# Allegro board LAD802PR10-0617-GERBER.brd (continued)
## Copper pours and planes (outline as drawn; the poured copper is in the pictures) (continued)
GND on BOTTOM (solid shape): 118.24,72.2 118.24,72 118.5,71.74 118.5,69.01 118.31,68.82 117.8,68.82 117.61,69.01 117.61,69.49 117.61,69.5 117.63,69.61 117.61,69.72 117.61,69.73 117.61,70.14 117.61,70.15 117.63,70.26 117.61,70.37 117.61,70.38 117.61,70.79 117.61,70.8 117.63,70.91 117.61,71.02 117.61,71.03 117.61,71.44 117.61,71.45 117.63,71.56 117.61,71.67 117.61,71.68 117.61,72.09 117.63,72.15 117.63,72.2 117.76,72.32 118.12,72.32
GND on BOTTOM (solid shape): 138.3,8.05 141.8,10.3 145.41,8.22 147.9,3.66 147.9,0.25 134.52,0.25
GND on BOTTOM (solid shape): 181.44,44.53 181.44,43.28 181.03,42.87 181.03,41.84 180.83,41.63 180.47,41.63 180.11,41.99 179.6,41.99 179.53,42.06 179.53,42.63 179.41,42.75 178.71,42.75 178.58,42.63 178.58,41.29 178.52,41.23 178.14,41.23 178.07,41.29 178.07,42.12 177.75,42.44 176.55,42.44 176.17,42.06 175.02,42.06 174.65,42.44 173.57,42.44 173.38,42.25 173.38,42.06 173.25,41.93 172.8,41.93 172.61,42.12 172.61,42.56 172.8,42.75 174.7,42.75 175.15,43.2 177.56,43.2 177.82,43.46 177.82,43.65 178.2,44.03 179.86,44.03 180.04,44.21 180.04,44.72 179.47,45.29 177.88,45.29 177.88,45.55 177.82,45.61 177.44,45.61 177.31,45.74 177.31,46.63 177.44,46.75 179.22,46.75
GND on BOTTOM (solid shape): 103.74,45.13 103.75,45.12 103.97,45.03 104.19,45.13 104.39,45.13 104.61,45.03 104.84,45.13 105.04,45.13 105.26,45.03 105.49,45.13 105.69,45.13 105.91,45.03 106.14,45.13 106.32,45.13 106.52,44.93 106.52,44.9 106.58,44.69 106.74,44.55 106.78,44.54 106.78,44.34 106.74,44.32 106.64,44.26 106.57,44.17 106.46,44.07 106.46,43.81 106.04,43.39 106,43.38 105.96,43.36 105.79,43.36 105.32,43.83 105.32,44.19 105.18,44.33 103.72,44.33 103.64,44.34 103.57,44.33 103.34,44.33 103.1,44.57 103.1,44.59 103.01,44.77 102.83,44.85 102.8,44.88 102.8,45.3 102.88,45.39 103.48,45.39
GND on BOTTOM (solid shape): 105.08,67.04 105.26,66.98 105.45,67.04 105.73,67.04 105.91,66.98 106.1,67.04 106.38,67.04 106.4,67.03 106.46,67 106.46,66.7 106.74,66.43 106.74,66.26 106.7,66.25 106.63,66.21 106.57,66.16 106.5,66.13 106.42,66.16 106.17,66.27 105.92,66.17 105.85,66.14 105.54,66.27 105.22,66.14 105.15,66.17 104.87,66.27 104.61,66.12 104.57,66.13 104.54,66.15 104.34,66.35 104.34,66.48 104.55,66.62 104.62,66.86 104.62,66.88 104.74,67.01 104.8,67.04
GND on BOTTOM (solid shape): outline of 91 points within 109.8,68.76 111.58,73.42
GND on BOTTOM (solid shape): outline of 153 points within 186.96,11.13 205.44,17.71
GND on BOTTOM (solid shape): 110.15,45.62 110.15,43.55 110.21,43.5 110.21,43.49 110.32,43.36 110.47,43.31 110.49,43.31 110.56,43.24 110.56,43.22 110.6,43.09 110.69,43 110.69,42.92 110.59,42.78 110.56,42.61 110.53,42.61 110.19,42.35 110.45,42.01 110.47,42.01 110.56,41.93 110.56,41.91 110.61,41.78 110.71,41.68 110.75,41.61 110.72,41.53 110.62,41.43 110.37,41.43 110.06,41.73 109.95,41.73 109.84,41.9 109.65,41.97 109.61,41.97 109.59,42 109.44,42.27 109.14,42.33 109.12,42.36 109.11,42.38 109.06,42.49 108.97,42.57 108.97,42.7 109.12,42.96 108.97,43.22 108.97,43.3 108.85,43.42 108.73,43.42 108.71,43.45 108.4,43.64 108.08,43.45 108.07,43.42 107.88,43.42 107.79,43.5 107.79,43.67 108.12,43.99 108.13,43.99 108.67,43.99 108.68,43.99 109.11,44.17 108.86,44.56 108.85,44.57 108.75,44.67 108.72,44.74 108.72,45.1 108.74,45.17 108.76,45.24 108.8,45.28 108.82,45.28 108.96,45.32 109.06,45.42 109.07,45.43 109.24,45.57 109.26,45.57 109.41,45.62 109.51,45.73 110.04,45.73
GND on BOTTOM (solid shape): outline of 206 points within 0.25,119.31 11.7,125.05
GND on BOTTOM (solid shape): outline of 110 points within 223.48,36.02 229.04,52.28
GND on BOTTOM (solid shape): 107.14,72.05 107.3,72.05 107.43,71.92 107.43,71.42 107.42,71.41 107.39,71.26 107.42,71.11 107.43,71.1 107.43,71.07 107.51,70.98 107.51,70.87 107.37,70.59 107.5,70.31 107.51,70.3 107.51,70.23 107.5,70.21 107.39,69.95 107.51,69.69 107.51,69.55 107.43,69.44 107.4,69.31 107.35,69.27 107.34,69.27 107.14,69.21 107.02,69.05 107.01,69.03 106.99,69 106.96,69 106.77,68.99 106.61,68.89 106.44,68.89 106.18,69.01 105.91,68.9 105.9,68.89 105.81,68.89 105.79,68.9 105.54,69.01 105.28,68.9 105.26,68.89 105.17,68.89 105.16,68.9 104.9,69.01 104.64,68.9 104.63,68.89 104.54,68.89 104.49,68.93 104.4,69.01 104.4,69.24 104.61,69.41 104.62,69.68 104.67,69.73 104.69,69.73 104.78,69.77 104.85,69.84 105.02,69.84 105.26,69.72 105.5,69.84 105.67,69.84 105.91,69.72 106.15,69.84 106.33,69.84 106.81,69.85 106.66,70.32 106.65,70.32 106.62,70.35 106.62,70.64 106.66,70.65 106.79,70.74 106.86,70.88 106.87,70.89 106.91,70.94 106.87,70.99 106.86,71.01 106.79,71.15 106.65,71.24 106.65,71.8 106.91,72.06
GND on BOTTOM (solid shape): outline of 216 points within 0.25,0.25 231.65,138.25
GND on IN1 (solid shape): 15.58,30.5 15.58,29.55 15.13,29.1 2.88,29.1 2.62,29.36 2.62,30.43 3,30.82 15.26,30.82
GND on IN1 (solid shape): 14.63,52.15 14.63,45.55 14.18,45.1 3.2,45.1 3.13,45.17 3.07,45.17 2.62,45.61 2.62,51.9 3.32,52.6 14.18,52.6
GND on IN1 (solid shape): 13.61,96.47 13.61,94 12.85,93.24 9.99,93.24 9.8,93.43 9.8,95.14 9.35,95.59 8.53,95.59 7.99,95.05 0.81,95.05 0.34,95.52 0.34,97.05 0.91,97.62 2.24,97.62 2.43,97.81 12.28,97.81
GND on IN1 (solid shape): 14.82,79.58 14.82,67.52 14.18,66.88 4.08,66.88 3.64,67.33 3.64,75.96 2.18,77.42 2.18,78.5 2.53,78.85 8.18,78.85 8.59,78.44 9.29,78.44 9.8,78.95 9.8,79.71 10.56,80.47 13.93,80.47
GND on IN1 (solid shape): 150.34,95.28 150.34,93.6 151.57,93.6 151.58,93.59 151.58,91.08 151.47,90.97 151.47,87.6 151.27,87.4 146.09,87.4 146.08,87.41 146.08,90.3 146.41,90.63 148.23,90.63 148.24,90.64 148.45,90.64 149.72,91.91 149.72,94.55 149.7,94.57 149.25,94.57 149.25,95.31 150.32,95.31
GND on IN1 (solid shape): 157.74,83.72 157.74,82.13 157.83,82.04 158.94,82.04 158.97,82.01 158.97,79.63 158.88,79.54 158.88,77.57 158.87,77.56 158.87,77.51 158.62,77.25 158.62,71.99 158.45,71.82 155.16,71.82 154.07,72.92 154.07,77.59 156.1,79.61 156.96,79.61 157.1,79.76 157.1,82.98 157.08,83 156.63,83 156.63,83.76 157.7,83.76
GND on IN1 (solid shape): 147.36,105.02 147.36,103.36 147.43,103.29 148.58,103.29 148.6,103.28 148.6,100.51 148.42,100.34 148.42,100.32 148.33,100.23 148.33,96.51 147.53,95.71 143.09,95.71 142.9,95.9 142.9,99.27 143.15,99.52 144.29,99.52 146.08,101.32 146.43,101.32 146.72,101.6 146.72,103.8 146.72,103.8 146.72,104.25 146.69,104.28 146.24,104.28 146.24,104.29 146.24,105 146.27,105.03 147.35,105.03
GND on IN1 (solid shape): outline of 224 points within 0.25,0.25 231.65,138.25
GND on IN2 (solid shape): 15.58,30.5 15.58,29.55 15.13,29.1 2.88,29.1 2.62,29.36 2.62,30.43 3,30.82 15.26,30.82
GND on IN2 (solid shape): 14.63,52.15 14.63,45.55 14.18,45.1 3.2,45.1 3.13,45.17 3.07,45.17 2.62,45.61 2.62,51.9 3.32,52.6 14.18,52.6
GND on IN2 (solid shape): 13.61,96.47 13.61,94 12.85,93.24 9.99,93.24 9.8,93.43 9.8,95.14 9.35,95.59 8.53,95.59 8.02,95.08 0.78,95.08 0.34,95.52 0.34,97.05 0.91,97.62 2.24,97.62 2.43,97.81 12.28,97.81
GND on IN2 (solid shape): 14.82,79.58 14.82,67.52 14.18,66.88 4.08,66.88 3.64,67.33 3.64,75.96 2.18,77.42 2.18,78.5 2.56,78.89 8.15,78.89 8.59,78.44 9.29,78.44 9.8,78.95 9.8,79.71 10.56,80.47 13.93,80.47
GND on IN2 (solid shape): 157.74,83.72 157.74,82.13 157.83,82.04 158.94,82.04 158.97,82.01 158.97,79.63 158.87,79.54 158.87,77.51 158.62,77.25 158.62,71.98 158.49,71.85 155.14,71.85 154.07,72.92 154.07,77.58 156.09,79.6 156.94,79.6 157.1,79.76 157.1,82.98 157.08,83 156.63,83 156.63,83.76 157.7,83.76
GND on IN2 (solid shape): 150.34,95.28 150.34,93.6 151.57,93.6 151.58,93.59 151.58,91.08 151.47,90.97 151.47,87.54 151.26,87.33 146.16,87.33 146.07,87.42 146.07,90.31 146.4,90.63 148.23,90.63 148.24,90.64 148.45,90.64 149.72,91.91 149.72,94.55 149.7,94.57 149.25,94.57 149.25,95.31 150.32,95.31
GND on IN2 (solid shape): 147.36,105.03 147.36,103.36 147.43,103.29 148.58,103.29 148.6,103.28 148.6,100.51 148.32,100.23 148.32,96.5 147.53,95.71 143.09,95.71 142.9,95.9 142.9,99.27 143.15,99.52 144.28,99.52 146.08,101.32 146.43,101.32 146.72,101.6 146.72,103.8 146.72,103.8 146.72,104.25 146.69,104.28 146.24,104.28 146.24,104.29 146.24,105 146.27,105.03 147.35,105.03
GND on IN2 (solid shape): outline of 227 points within 0.25,0.25 231.65,138.25
GND on BOTTOM: 34.7,90.19 76.59,90.19 77.46,89.31 77.46,85.73 76.94,85.21 76.94,85.17 76.49,84.71 76.49,22.79 77.46,21.81 77.46,18.22 77.45,18.2 59.65,18.2 59.21,18.64 45.94,18.64 44.74,19.84 42.34,19.84 41.46,20.72 41.46,23.02 39.77,24.71 35.69,24.71 34.81,25.6 34.81,29.29 32.86,31.23 32.86,88.35 ; 10 cut-outs
GND on BOTTOM: 87.76,9.68 88.17,9.68 88.64,9.21 88.64,5.25 87.97,4.58 87.97,3.92 88.23,3.65 88.59,3.65 88.77,3.83 88.77,4.11 88.97,4.31 89.26,4.31 89.47,4.11 89.47,3.5 89.06,3.09 87.5,3.09 87.07,3.52 87.07,5.1 87.65,5.68 87.65,9.57
GND on VCC: 2.6,0.26 2.07,0.47 1.85,1 1.85,7.1 2.07,7.63 2.6,7.85 3.65,7.85 4.62,8.34 4.8,9.42 26.6,9.42 27.11,9.93 34.99,9.93 35.71,10.65 36.84,11.8 36.91,11.87 36.9,17.16 34.74,19.3 34.56,19.38 32.05,19.39 31.92,19.26 29.94,19.26 29.61,18.94 29.61,18.2 29.94,17.87 32.6,17.87 32.85,17.62 32.85,17.35 32.84,14.33 31.83,13.33 29.13,13.32 28.85,13.61 28.86,14.04 28.86,14.04 28.86,14.14 28.86,14.25 28.86,14.25 28.85,15.88 28.72,16 28.72,17.54 28.58,17.68 25.34,17.68 25.16,17.86 25.16,18.32 25.23,18.39 25.23,18.49 25.16,18.55 25.16,22.26 25.48,22.58 25.48,24.59 24.97,25.1 24.97,25.28 24.83,25.42 23.73,25.42 23.54,25.23 17.2,25.23 17.19,25.24 17.09,25.23 16.99,25.23 16.98,25.23 16.92,25.16 0.8,25.16 1.04,25.5 1.43,25.65 2,25.86 2.41,26.31 27.68,26.31 28.51,27.13 30.97,27.13 31.39,26.71 31.39,25.27 31.14,25.02 31.14,23.15 31.79,22.5 33.44,22.5 40.15,15.79 40.15,0.26
GND on VCC: outline of 256 points within 0.26,11.83 228.37,138.25
GND on GND: outline of 262 points within 0.26,0.26 231.64,138.25
VCCSA_B+ on TOP (solid shape): 153.12,70.06 153.12,68.79 152.86,68.53 151.02,68.53 150.9,68.66 150.9,70.12 150.96,70.19 152.99,70.19
VCCSA_B+ on BOTTOM (solid shape): 153.83,69.87 153.83,68.44 153.76,68.37 153.53,68.37 153.53,68.93 153.1,68.93 153.1,68.37 152.8,68.37 152.7,68.47 151.54,68.47 150.94,67.88 150.94,67.68 150.94,67.63 150.94,67.57 150.94,67.36 151.1,67.21 151.51,67.21 151.59,67.12 151.59,65.34 151.51,65.26 150.42,65.26 150.32,65.36 150.32,69.82 150.56,70.07 153.63,70.07
VIN_+VCCEOPIO on TOP (solid shape): 99.78,117.9 99.78,115.33 99.65,115.21 98.6,115.21 98.32,115.49 98.32,117.87 98.57,118.13 99.55,118.13
VIN_+VCCEOPIO on BOTTOM (solid shape): 99.78,117.89 99.78,115.27 99.65,115.14 99.65,113.3 99.43,113.08 99.43,111.64 99.33,111.54 99.22,111.54 99.13,111.63 99.13,112.81 98.45,113.49 96.92,113.49 96.48,113.94 96.48,114.98 96.99,114.98 96.99,115.49 96.99,115.49 96.48,115.49 96.48,115.78 96.99,115.78 96.99,116.29 96.48,116.29 96.48,117.73 96.87,118.13 99.54,118.13
+DCBAT_LCD on TOP (solid shape): 225.51,51.26 230.08,51.26 230.21,51.14 230.21,49.36 229.89,49.04 225.06,49.04 224.82,49.28 224.82,49.59 224.7,49.71 223.26,49.71 223.04,49.5 222.65,49.5 222.59,49.56 222.59,50.62 222.67,50.7 222.69,50.7 222.81,50.82 223.1,50.82 223.23,50.95 223.23,51.46 223.41,51.64 225.13,51.64
+DCBAT_LCD on BOTTOM (solid shape): 225.45,50.88 225.45,49.36 225.32,49.23 224.81,49.23 224.68,49.36 222.78,49.36 222.59,49.55 222.59,50.63 222.78,50.82 223.22,50.82 223.48,51.07 225.25,51.07
+LAN_VDD33 on TOP (solid shape): 38.17,115.03 39.12,115.03 39.26,114.89 39.26,114.33 38.49,113.56 36.41,113.56 36.28,113.68 36.28,115.33 36.38,115.43 37.77,115.43
+LAN_VDD33 on BOTTOM (solid shape): 32.34,121.37 32.34,120.48 32.15,120.29 28.44,120.29 28.34,120.4 28.34,121.27 28.57,121.51 30.88,121.51 30.88,122 31.71,122
+LAN_VDD33 on BOTTOM (solid shape): 37.36,115.4 37.74,115.4 37.86,115.28 37.86,115.27 38.06,115.08 38.06,114.45 37.87,114.25 37.43,114.25 36.85,114.83 36.4,115.28 36.4,115.47 36.47,115.53 37.23,115.53
+LAN_VDD33 on IN1 (solid shape): 32.47,121.05 32.47,120.03 32.41,119.97 31.07,119.97 30.63,120.41 30.63,120.73 31.14,121.24 32.28,121.24
+LAN_VDD33 on IN1 (solid shape): 37.29,116.1 37.29,115.97 37.93,115.33 37.93,114.32 37.8,114.19 37.1,114.19 36.28,115.02 36.28,116.16 36.41,116.29 37.1,116.29
+LCDVDD on BOTTOM (solid shape): 225.17,26.9 225.17,25.82 224.87,25.52 223.56,25.52 223.56,25.52 222.39,25.52 222.19,25.72 222.19,26.86 222.6,27.27 224.8,27.27
+LCDVDD_LCD on TOP (solid shape): 224.1,47.69 224.1,46.29 224.05,46.24 222.4,46.24 222.14,46.5 222.14,47.52 222.39,47.76 224.02,47.76
+LCDVDD_LCD on BOTTOM (solid shape): 225.34,29.01 225.34,27.69 225.16,27.51 224.56,27.51 224.55,27.51 222.33,27.51 222.21,27.64 222.21,28.91 222.58,29.28 225.07,29.28
+LCDVDD_LCD on BOTTOM (solid shape): 223.53,47.76 224.68,47.76 224.87,47.57 224.87,46.56 224.68,46.37 223.48,46.37 223.37,46.25 222.4,46.25 222.15,46.51 222.15,47.59 222.41,47.85 223.43,47.85
+LCDVDD_LCD on IN1 (solid shape): outline of 191 points within 222.14,27.5 230.11,48.79
+TPAN_VDD on TOP (solid shape): 224.68,33.86 224.68,30.75 224.94,30.5 224.94,29.42 224.75,29.23 223.03,29.23 222.84,29.42 222.84,30.75 222.91,30.82 222.91,33.86 223.03,33.99 224.56,33.99
+TPAN_VDD on BOTTOM (solid shape): 224.68,30.56 224.68,30.11 224.18,29.6 222.93,29.6 222.7,29.84 222.7,30.43 222.98,30.71 224.53,30.71
+TPAN_VDD_F on TOP (solid shape): 230.59,35.2 230.59,30.94 230.14,30.5 227.79,30.5 227.41,30.12 227.41,29.29 227.16,29.04 225.89,29.04 225.6,29.32 225.6,30.4 227.73,32.53 227.73,33.8 228.19,34.26 228.19,35.31 228.39,35.51 230.27,35.51
ACIN_CHG on BOTTOM (solid shape): 192.87,34.44 192.87,34.38 192.55,34.06 192.55,33.49 192.49,33.42 191.92,33.42 191.79,33.55 191.79,33.84 191.79,33.85 191.81,33.95 191.79,34.06 191.79,34.07 191.79,34.38 191.92,34.5 192.8,34.5
ADJ_2.5V on BOTTOM (solid shape): 45.04,9.73 45.04,8.89 45.18,8.76 46.18,8.76 46.47,8.46 48.15,8.46 48.34,8.27 48.34,7.75 48.23,7.64 46.54,7.64 46.11,8.07 44.36,8.07 44.19,8.24 44.19,9.64 44.36,9.81 44.96,9.81
AUD_AGND on VCC, GND: 4.47,9.93 4.09,10.17 3.65,10.25 2.3,10.25 1.99,10.39 1.85,10.7 1.85,13.67 1.99,13.98 2.3,14.11 12.45,14.11 13.19,14.74 12.71,15.58 12.71,20.96 13.19,21.8 12.45,22.42 1.2,22.42 0.89,22.55 0.76,22.87 0.76,24.66 16.94,24.66 16.95,24.65 17.05,24.66 17.08,24.66 17.16,24.66 17.21,24.73 23.75,24.73 23.94,24.92 24.79,24.92 25.23,24.48 25.23,22.68 24.91,22.36 24.91,17.75 25.24,17.42 28.47,17.42 28.47,16.01 28.34,15.88 28.35,14.15 28.34,13.62 28.48,13.26 28.77,12.96 28.77,12.96 28.84,12.89 28.92,12.81 28.92,12.81 29.02,12.81 29.13,12.81 29.13,12.81 31.93,12.83 32.04,12.82 32.04,12.83 32.11,12.9 33.34,14.12 33.34,14.48 33.36,17.24 33.36,17.45 33.36,17.66 33.21,17.8 33.03,17.8 32.71,18.12 30.04,18.12 29.86,18.3 29.86,18.83 30.04,19.01 31.92,19.01 32.04,18.88 34.46,18.87 36.39,16.95 36.4,12.83 36.4,12.08 35.27,10.93 34.77,10.44 26.9,10.44 26.39,9.93
AUD_SPK_L+ on TOP (solid shape): 34.05,9.1 34.05,7.96 33.8,7.71 32.2,7.71 32.09,7.81 32.09,9.13 32.32,9.35 33.81,9.35
AUD_SPK_L+ on TOP (solid shape): 32.91,19.84 32.91,19.65 32.79,19.52 31.81,19.52 31.81,19.52 31.07,19.52 30.94,19.65 30.05,19.65 29.99,19.71 29.99,19.84 30.05,19.9 31.9,19.9 31.96,19.96 32.79,19.96
AUD_SPK_L+ on IN1 (solid shape): 35.13,9.36 35.13,9.1 34.15,8.12 33.42,8.12 33.23,8.31 33.23,9.5 33.6,9.87 34.63,9.87
AUD_SPK_L+ on IN1 (solid shape): 33.26,19.93 35.99,19.93 36.53,19.39 36.53,18.95 36.09,18.5 35.58,18.5 34.75,19.33 31.9,19.33 31.77,19.45 31.77,19.84 31.9,19.96 33.23,19.96
AUD_SPK_L+_C on TOP (solid shape): 28.34,8.72 29.48,8.72 29.93,8.28 30.94,8.28 31.01,8.34 31.01,8.91 31.13,9.04 31.83,9.04 31.91,8.97 31.91,7.72 31.7,7.52 27.7,7.52 27.15,8.07 27.15,9.12 27.32,9.29 27.77,9.29
AUD_SPK_L+_C on BOTTOM (solid shape): 10.11,6.35 10.11,4.8 10.49,4.42 10.6,4.42 10.73,4.3 10.73,3.92 10.59,3.79 9.65,3.79 9.49,3.96 9.49,6.45 9.6,6.57 9.89,6.57
AUD_SPK_L+_C on IN1 (solid shape): 27.88,8.9 27.88,8.28 27.19,7.59 25.58,7.59 25.47,7.7 25.47,8.66 25.6,8.79 26.69,8.79 27.08,9.18 27.6,9.18
AUD_SPK_L+_C on IN1 (solid shape): 12.74,4.84 12.74,4.63 12.03,3.92 9.63,3.92 9.5,4.05 9.5,4.75 9.68,4.93 11.59,4.93 12.05,5.4 12.18,5.4
AUD_SPK_L- on TOP (solid shape): 34.05,6.95 34.05,6.09 33.65,5.68 32.29,5.68 32.1,5.88 32.1,6.9 32.33,7.14 33.86,7.14
AUD_SPK_L- on TOP (solid shape): 33.04,20.47 33.04,20.15 32.98,20.09 32.71,20.09 32.61,20.11 32.5,20.09 32.46,20.09 32.35,20.11 32.24,20.09 32.13,20.09 32.02,20.11 31.91,20.09 31.83,20.09 31.77,20.03 30.05,20.03 29.99,20.09 29.99,20.22 30.05,20.28 31.64,20.28 31.96,20.6 32.91,20.6
AUD_SPK_L- on IN1 (solid shape): 35.22,21.33 35.22,20.36 35.18,20.32 34.77,20.32 34.77,20.32 34.48,20.32 34.31,20.15 32.02,20.15 31.9,20.28 31.9,20.41 32.34,20.85 33.93,20.85 34.48,21.4 35.15,21.4
AUD_SPK_L- on IN1 (solid shape): 35.83,7.99 35.83,7.66 35.1,6.94 34.75,6.94 33.86,6.06 33.79,5.98 33.11,5.98 32.98,6.11 32.98,7.17 33.33,7.52 34.2,7.52 34.72,8.05 34.72,8.05 35.1,8.42 35.4,8.42
AUD_SPK_L-_C on TOP (solid shape): 31.88,6.97 31.88,5.91 31.8,5.84 31.32,5.84 31.2,5.96 31.2,6.18 31.01,6.37 29.86,6.37 29.1,5.61 28.4,5.61 28.1,5.31 27.33,5.31 27.2,5.45 27.2,6.47 27.42,6.7 28.02,6.7 28.27,6.95 28.27,6.98 28.43,7.14 31.71,7.14
AUD_SPK_L-_C on BOTTOM (solid shape): 9.1,6.35 9.1,3.33 8.91,3.14 8.32,3.14 8.19,3.27 8.19,6.37 8.19,6.38 8.36,6.55 8.9,6.55
AUD_SPK_L-_C on IN1 (solid shape): 27.93,6.47 27.93,5.61 27.71,5.38 26.58,5.38 26.19,5.77 26.19,6.65 26.27,6.73 27.67,6.73
AUD_SPK_L-_C on IN1 (solid shape): 9.11,4.55 9.11,3.85 9.42,3.54 9.82,3.54 9.85,3.51 9.85,2.57 9.73,2.45 8.69,2.45 8.1,3.03 8.1,4.48 8.19,4.58 9.09,4.58
AUD_SPK_R+ on TOP (solid shape): 34.05,5.14 34.05,4.02 33.93,3.9 32.19,3.9 32.09,4 32.09,5.08 32.27,5.26 33.94,5.26
AUD_SPK_R+ on TOP (solid shape): 33.36,21.99 33.36,21.99 33.48,21.86 33.48,21.62 33.23,21.36 31.64,21.36 31.13,20.85 30.05,20.85 29.99,20.92 29.99,21.04 30.05,21.1 30.93,21.1 31.99,22.15 33.2,22.15
AUD_SPK_R+ on IN1 (solid shape): 35.58,5.61 35.58,5.31 34.36,4.09 33.55,4.09 33.36,4.28 33.36,5.05 33.6,5.29 33.84,5.29 34.75,6.21 34.98,6.21
AUD_SPK_R+ on IN1 (solid shape): 34.65,22.81 34.65,21.9 34.53,21.78 34.31,21.78 34.06,21.54 33.73,21.65 33.47,21.42 32.47,21.42 32.34,21.55 32.34,21.75 32.4,21.82 32.4,21.86 32.64,22.1 32.92,22.1 33.71,22.89 34.58,22.89
AUD_SPK_R+_C on TOP (solid shape): 31.91,4.9 31.91,3.81 31.61,3.52 27.93,3.52 27.88,3.57 27.65,3.57 27.16,4.06 27.16,4.79 27.29,4.91 27.83,4.91 28.02,4.72 29.05,4.72 29.1,4.71 29.15,4.7 29.63,4.21 30.09,4.21 30.21,4.34 30.94,4.34 31.01,4.41 31.01,4.91 31.13,5.04 31.77,5.04
AUD_SPK_R+_C on BOTTOM (solid shape): 12.67,8.78 12.67,7.74 12.41,7.48 12.41,5.07 12.22,4.88 11.58,4.88 11.49,4.97 11.49,8.83 11.62,8.96 12.48,8.96
AUD_SPK_R+_C on IN2 (solid shape): 27.77,4.78 27.77,3.89 27.64,3.76 26.69,3.76 26.5,3.96 26.5,4.78 26.63,4.91 27.64,4.91
AUD_SPK_R+_C on IN2 (solid shape): 12.78,8.81 12.78,7.86 12.53,7.61 12.11,7.61 12.04,7.67 11.64,7.67 11.51,7.8 11.51,8.75 11.7,8.94 12.66,8.94
AUD_SPK_R- on TOP (solid shape): 34.09,2.98 34.09,1.83 33.83,1.58 32.26,1.58 32.05,1.79 32.05,2.77 32.32,3.04 34.02,3.04
AUD_SPK_R- on TOP (solid shape): 32.21,21.17 32.21,20.85 32.09,20.72 31.83,20.72 31.52,20.41 30.05,20.41 29.99,20.47 29.99,20.6 30.12,20.72 31.19,20.72 31.25,20.79 31.26,20.79 31.7,21.23 31.74,21.23 31.78,21.23 32.15,21.23
AUD_SPK_R- on IN1 (solid shape): 33.22,23.07 33.22,22.93 32.09,21.8 32.09,21.3 32.21,21.17 32.21,20.98 31.58,20.34 31.2,20.34 30.88,20.66 30.88,22.2 32.37,23.69 32.6,23.69
AUD_SPK_R- on IN1 (solid shape): 35.62,2.78 35.62,2.51 34.92,1.8 33.42,1.8 33.29,1.93 33.29,2.94 33.49,3.14 34.45,3.14 34.77,3.46 34.94,3.46
AUD_SPK_R-_C on TOP (solid shape): 31.89,3.07 31.89,1.86 31.77,1.74 31.26,1.74 31.2,1.8 31.2,2.18 31.01,2.37 29.81,2.37 29.05,1.61 28.4,1.61 28.12,1.33 27.39,1.33 27.2,1.52 27.2,2.25 28.09,3.14 31.83,3.14
AUD_SPK_R-_C on BOTTOM (solid shape): 11.11,8.3 11.11,5.02 10.97,4.88 10.63,4.88 10.49,5.02 10.49,6.5 10.42,6.57 10.42,6.93 10.25,7.1 10.08,7.1 9.93,7.26 9.93,7.7 10.56,8.34 11.07,8.34
AUD_SPK_R-_C on IN2 (solid shape): 27.9,2.37 27.9,1.48 27.77,1.35 26.69,1.35 26.56,1.48 26.56,2.43 26.63,2.49 27.77,2.49
AUD_SPK_R-_C on IN2 (solid shape): 11.1,7.8 11.1,7.36 11.17,7.29 11.89,7.29 12,7.18 12,6.24 11.83,6.07 10.87,6.07 10.86,6.08 10.01,6.08 9.71,6.38 9.71,7.59 10.04,7.92 10.98,7.92
BST_1.2V_R on BOTTOM (solid shape): 84.03,105.94 84.03,104.41 83.97,104.35 83.52,104.35 83.08,104.79 83.08,105.94 83.14,106 83.97,106
BST_3V on BOTTOM (solid shape): 174.77,44.92 174.77,43.78 174.71,43.71 174.58,43.71 174.52,43.78 174.52,44.22 173.97,44.77 173.88,44.91 173.74,45 173.5,45.24 172.99,45.24 172.93,45.3 172.93,45.74 173.06,45.87 173.82,45.87
BST_5V on BOTTOM (solid shape): 177.56,36.22 177.56,34.69 177.5,34.63 177.5,33.87 177.37,33.74 177.31,33.74 177.25,33.81 177.25,34.76 176.87,35.14 176.87,36.16 176.99,36.28 177.5,36.28
BST_+1VALW on BOTTOM (solid shape): 149.75,45.55 149.75,43.84 149.69,43.78 149.62,43.78 149.56,43.84 149.56,43.89 149.56,44.09 148.29,45.36 148.29,46 148.35,46.06 149.24,46.06
BST_+1VALW_R on BOTTOM (solid shape): 149.31,47.39 149.31,46.82 149.24,46.76 148.35,46.76 148.25,46.66 148.25,46.53 148.04,46.32 147.47,46.32 147.4,46.38 147.4,46.89 147.97,47.46 149.24,47.46
BST_R_+VCCEOPIO on BOTTOM (solid shape): 95.59,110.7 95.59,108.79 95.46,108.67 94.95,108.67 94.83,108.79 94.83,110.7 94.89,110.76 95.52,110.76
CORE_SNUB on TOP (solid shape): 152.48,82.06 152.48,79.58 152.17,79.27 151.4,79.27 151.34,79.33 151.34,82 151.47,82.12 152.42,82.12
CORE_SW on BOTTOM (solid shape): 155.8,82.57 155.91,82.45 156.83,82.45 156.86,82.42 156.86,80.47 156.84,80.44 156.03,80.44 155.23,79.65 152.55,79.65 152.48,79.71 152.48,81.04 153.44,81.04 153.44,81.93 152.48,81.93 152.48,83.2 152.61,83.33 155.04,83.33
CPU_B+ on TOP (solid shape): 160.67,82.79 160.67,79.63 160.71,79.59 160.71,72.08 160.45,71.82 159.2,71.82 158.95,72.08 158.95,77.23 159.06,77.35 159.06,78.82 159.1,78.86 159.1,79.53 159.12,79.55 159.12,82.81 159.16,82.84 160.61,82.84
CPU_B+ on BOTTOM (solid shape): 159.93,83.67 159.93,82.91 160.01,82.82 160.63,82.82 160.66,82.79 160.66,79.09 161.32,78.43 163.21,78.43 163.36,78.28 163.36,77.31 163.38,77.31 163.38,77.26 163.86,77.26 163.86,76.86 163.38,76.86 163.38,76.81 163.36,76.81 163.36,76.11 163.38,76.11 163.38,76.06 163.86,76.06 163.86,75.66 163.38,75.66 163.38,75.61 163.36,75.61 163.36,74.94 163.34,74.92 163.34,73.43 164.29,72.47 164.29,67.6 164.2,67.37 164.29,67.13 164.29,67.08 163.74,66.53 153.1,66.53 152.75,66.88 152.75,68.24 153.22,68.24 153.22,68.8 153.41,68.8 153.41,68.24 155,68.24 155.35,67.89 158.13,67.89 158.99,68.75 158.99,77.22 159.08,77.32 159.08,78.65 159.16,78.73 159.16,79.38 159.15,79.39 159.15,81.22 159.14,81.23 159.14,82.82 159.34,82.82 159.35,82.83 159.5,82.83 159.67,82.99 159.67,83.7 159.72,83.74 159.86,83.74
CPU_B+ on IN1 (solid shape): 160.69,78.75 160.69,72.02 160.46,71.79 159.24,71.79 158.95,72.08 158.95,77.18 159.06,77.29 159.06,78.83 159.23,78.99 160.45,78.99
CPU_B+ on IN2 (solid shape): 160.71,78.75 160.71,72.04 160.48,71.81 159.23,71.81 158.96,72.08 158.96,77.2 159.07,77.31 159.07,78.84 159.23,78.99 160.47,78.99
EN_2.5V on BOTTOM (solid shape): 54.67,9.61 54.67,8.74 54.6,8.68 54.6,7.91 54.36,7.66 51.79,7.66 51.59,7.86 51.59,8.23 51.71,8.35 53.68,8.35 53.97,8.64 53.97,9.58 54.09,9.7 54.58,9.7
GPU_B+ on TOP (solid shape): 150.27,103.98 150.27,100.79 150.64,100.42 150.64,96.27 150.48,96.11 148.75,96.11 148.67,96.18 148.67,100.31 148.75,100.38 148.75,103.97 148.87,104.09 150.16,104.09
GPU_B+ on TOP (solid shape): 153.26,94.36 153.26,91.24 153.6,90.9 153.6,87.38 153.47,87.25 151.79,87.25 151.75,87.3 151.75,89.04 151.73,89.06 151.73,94.36 151.75,94.38 153.23,94.38
GPU_B+ on BOTTOM (solid shape): 149.56,104.95 149.56,104.16 149.63,104.09 150.27,104.09 150.3,104.07 150.3,101.2 151.09,100.41 151.09,100.4 153.36,100.4 153.38,100.38 153.76,100.38 154.2,99.94 155.02,99.94 155.02,99.97 155.35,99.97 155.35,100.46 155.8,100.46 155.8,99.94 156.22,99.94 156.22,99.97 156.55,99.97 156.55,100.46 157,100.46 157,99.94 157.59,99.94 157.6,99.93 159.25,99.93 159.26,99.94 159.58,99.94 161.21,98.3 161.22,98.29 161.42,97.75 161.69,97.23 161.69,91.01 161.25,90.58 159.68,90.58 156.44,87.33 151.81,87.33 151.71,87.43 151.71,94.38 152.19,94.38 152.26,94.45 152.26,95.22 152.35,95.31 152.46,95.31 152.54,95.22 152.54,94.49 152.65,94.38 153.23,94.38 153.25,94.36 153.25,91.55 153.67,91.14 156.55,91.14 157.56,92.15 157.56,96.53 156.82,97.27 149.91,97.27 149.24,96.6 149.24,96.12 149.19,96.07 148.71,96.07 148.64,96.14 148.64,100.32 148.75,100.42 148.75,104.09 148.99,104.09 149,104.1 149.24,104.1 149.28,104.15 149.28,104.93 149.37,105.02 149.49,105.02
GT_SNUB1 on TOP (solid shape): 147.47,92.03 147.47,91.14 147.34,91.01 145.56,91.01 145.37,91.2 144.42,91.2 144.29,91.33 144.29,92.03 144.42,92.16 147.34,92.16
GT_SNUB2 on TOP (solid shape): 144.32,102.32 144.32,101.28 143.76,100.72 143.76,100.22 143.64,100.11 142.67,100.11 142.48,100.3 142.48,102.23 142.6,102.35 144.28,102.35
GT_SW1 on BOTTOM (solid shape): 148.41,93.99 149.46,93.99 149.47,93.98 149.47,92.03 148.43,92.03 147.29,90.89 145.18,90.89 145.05,91.01 145.05,92.35 146.01,92.35 146.01,93.24 145.05,93.24 145.05,94.7 145.12,94.76 147.64,94.76
GT_SW2 on BOTTOM (solid shape): 145.39,103.71 146.45,103.71 146.49,103.67 146.49,101.73 145.68,101.73 143.73,99.78 142.45,99.78 142.07,100.16 142.07,102.06 142.96,102.06 142.96,102.95 142.07,102.95 142.07,104.29 142.26,104.48 144.63,104.48
HDMI_PLL_GND on TOP (solid shape): 24.4,80.16 24.4,79.33 23.9,78.82 23.13,78.82 22.12,77.81 17.29,77.81 16.66,78.44 16.66,79.65 17.1,80.09 21.86,80.09 22.25,80.47 24.09,80.47
IR_GND on BOTTOM (solid shape): 227.99,38 227.99,37.16 227.81,36.98 225.44,36.98 225.13,37.29 224.78,37.29 224.69,37.38 223.59,37.38 223.49,37.48 223.49,38.12 223.59,38.22 227.78,38.22
LDO_+1VALW on BOTTOM (solid shape): 149.5,42.25 149.5,41.67 149.37,41.55 147.78,41.55 147.72,41.61 147.72,41.86 147.98,42.12 148.17,42.12 148.42,42.37 149.37,42.37
LG_1.2V on BOTTOM (solid shape): 86.89,105.49 86.89,104.73 86.38,104.22 86.19,104.22 86.06,104.35 86.06,105.17 86.44,105.56 86.82,105.56
LG_1.2V on BOTTOM (solid shape): 78.32,103.65 78.32,103.33 78.13,103.14 78.13,102.76 77.91,102.55 77.15,102.55 77.01,102.68 77.01,102.89 77.87,103.75 78.21,103.75
LG_1.2V on IN1 (solid shape): 79.01,104.03 79.01,103.54 78.04,102.56 77.08,102.56 76.99,102.65 76.99,102.9 78.25,104.16 78.89,104.16
LG_1.2V on IN1 (solid shape): 86.57,105.3 86.57,104.23 85.96,103.62 85.8,103.62 85.47,103.95 85.47,104.2 86,104.73 86,105.24 86.13,105.36 86.51,105.36
LGATE_CHG on BOTTOM (solid shape): 204.11,35.9 204.11,35.27 203.92,35.08 203.16,35.08 203.03,35.2 203.03,36.03 203.09,36.09 203.92,36.09
LGATE_CHG on BOTTOM (solid shape): 198.58,36.22 198.58,35.96 198.2,35.58 197.38,35.58 197.31,35.52 196.11,35.52 196.04,35.58 196.04,35.65 196.11,35.71 197.06,35.71 197.16,35.81 197.16,35.81 197.64,36.28 198.52,36.28
LGATE_CHG on IN2 (solid shape): 200.04,36.85 200.04,36.28 199.92,36.16 198.96,36.16 198.58,35.77 197.63,35.77 197.5,35.9 197.5,36.28 198.33,37.11 199.79,37.11
LGATE_CHG on IN2 (solid shape): 204.04,36.66 204.04,35.64 203.95,35.55 203.16,35.55 202.84,35.87 202.84,36.91 202.97,37.04 203.66,37.04
LX_1.2V on BOTTOM (solid shape): 86.51,105.94 86.51,105.81 86.44,105.75 86.25,105.75 85.75,105.24 85.75,104.86 85.24,104.35 84.41,104.35 84.35,104.41 84.35,104.98 84.73,105.36 85.05,105.36 85.68,106 86.44,106
LX_1.2V on BOTTOM (solid shape): 76.9,106.34 76.9,105.41 77.34,104.97 80.35,104.97 80.38,104.94 80.38,103.94 80.35,103.9 77.35,103.9 76.46,103.02 74.12,103.02 74,103.14 74,106.57 74.12,106.7 76.54,106.7
LX_1.2V on IN2 (solid shape): 78.19,105.05 78.19,104.22 78.06,104.09 76.86,104.09 76.66,104.29 76.66,105.11 76.79,105.24 78,105.24
LX_1.2V on IN2 (solid shape): 85.75,105.49 85.75,104.79 85.5,104.55 84.52,104.55 84.23,104.84 84.23,105.37 84.48,105.62 85.62,105.62
LX_1.8VALW on BOTTOM (solid shape): 166.71,35.71 166.71,33.68 166.52,33.49 163.53,33.49 162.24,34.78 161.2,34.78 161.11,34.87 161.11,35.54 161.22,35.65 163.15,35.65 163.47,35.96 166.45,35.96
LX_3V on BOTTOM (solid shape): 172.68,45.81 172.68,45.17 173.29,44.56 173.38,44.41 173.53,44.32 173.95,43.9 174.14,43.9 174.48,43.56 174.48,43 174.39,42.91 172.71,42.91 172.36,42.56 172.36,40.85 172.17,40.66 169.37,40.66 169.18,40.85 169.18,43.9 171.15,45.87 172.61,45.87
LX_3V on IN2 (solid shape): 177.25,44.21 177.25,43.96 177.12,43.83 174.14,43.83 173.31,43.01 172.99,43.01 172.87,43.13 172.87,43.39 173.82,44.34 177.12,44.34
LX_5V on TOP (solid shape): 176.99,34.05 180.3,34.05 180.36,34.12 180.61,34.12 180.74,33.99 180.74,33.74 180.49,33.48 176.68,33.48 176.18,33.98 175.51,33.98 175.46,34.04 175.46,34.5 175.5,34.54 176.51,34.54
LX_5V on BOTTOM (solid shape): 175.22,35.77 175.22,35.14 175.79,34.56 176.8,34.56 177.06,34.31 177.06,33.74 177.06,33.74 177.06,33.04 176.99,32.98 170.01,32.98 169.75,33.23 169.75,35.52 170.14,35.9 175.09,35.9
LX_+1VALW on BOTTOM (solid shape): 147.15,47.65 147.15,46.19 147.4,45.93 148.04,45.93 148.1,45.87 148.1,45.17 149.41,43.86 149.43,43.78 149.43,43.08 149.31,42.95 147.78,42.95 147.53,42.7 147.53,41.62 147.4,41.49 145.18,41.49 144.93,41.74 144.93,47.78 145.12,47.97 146.83,47.97
LX_+1VALW on IN2 (solid shape): 148.93,44.21 152.93,44.21 153.12,44.02 153.12,43.64 153.06,43.58 148.67,43.58 148.29,43.96 148.29,44.21 148.48,44.4 148.74,44.4
MCT on TOP (solid shape): 20.93,118.57 20.93,117.22 20.69,116.98 20.69,107.9 20.48,107.69 19.91,107.69 19.62,107.99 19.62,112.44 19.3,112.76 19.3,118.41 19.66,118.77 20.73,118.77
MCT on BOTTOM (solid shape): 20.86,120.25 20.86,118.11 20.63,117.87 19.88,117.87 19.62,118.14 19.62,120.25 19.77,120.4 20.71,120.4
MCT0 on TOP (solid shape): 19.26,109.05 19.26,108.03 19.13,107.9 17.67,107.9 17.61,107.97 17.61,109.05 17.67,109.11 19.2,109.11
MCT0 on BOTTOM (solid shape): 18.5,108.79 19.96,108.79 20.21,108.54 20.21,108.03 20.09,107.9 19.64,107.9 19.63,107.91 17.94,107.91 17.93,107.9 17.74,107.9 17.55,108.1 17.55,108.92 17.74,109.11 18.18,109.11
MCT1 on TOP (solid shape): 19.26,112.44 19.26,111.52 19.2,111.46 17.74,111.46 17.66,111.54 17.66,112.44 17.86,112.64 19.06,112.64
MCT1 on BOTTOM (solid shape): 18.17,112.44 20.02,112.44 20.27,112.18 20.27,111.42 20.21,111.36 17.83,111.36 17.67,111.52 17.67,112.37 17.67,112.4 17.83,112.55 18.06,112.55
PHASE_CHG on TOP (solid shape): 207.73,34.95 207.73,32.47 208.3,31.9 209.51,31.9 209.7,31.7 209.7,30.43 209.54,30.28 206.49,30.28 206.01,30.76 206.01,34.95 206.2,35.14 207.54,35.14
PHASE_CHG on BOTTOM (solid shape): 210.33,35.14 210.33,30.38 209.76,29.81 206.08,29.81 205.95,29.93 205.95,32.15 205.38,32.73 204.81,32.73 204.68,32.85 204.68,35.39 204.81,35.52 209.95,35.52
PHASE_CHG on BOTTOM (solid shape): 199.15,35.52 199.15,35.08 199.03,34.95 197.44,34.95 197.25,35.14 196.11,35.14 196.04,35.2 196.04,35.27 196.11,35.33 197.06,35.33 197.12,35.39 197.37,35.39 197.38,35.39 197.44,35.46 198.25,35.46 198.33,35.46 198.52,35.65 199.03,35.65
PHASE_CHG on IN2 (solid shape): 207.6,34.82 207.6,34 207.41,33.81 205.95,33.81 205.76,34 205.76,34.57 206.2,35.01 207.41,35.01
PHASE_CHG on IN2 (solid shape): 197.58,35.65 198.64,35.65 198.64,35.65 199.98,35.65 200.17,35.46 200.17,35.01 199.98,34.82 199.35,34.82 199.22,34.95 197.38,34.95 197.25,35.08 197.25,35.39 197.5,35.65
RING2 on TOP (solid shape): 23.83,20.72 24.72,20.72 24.79,20.66 24.79,20.53 24.72,20.47 23.58,20.47 23.45,20.59 22.56,20.59 22.37,20.78 22.37,20.97 22.56,21.16 23.39,21.16
RING2 on BOTTOM (solid shape): 24.4,15.32 24.4,14.94 24.15,14.69 21.67,14.69 21.61,14.62 21.29,14.62 21.23,14.69 21.23,15.26 21.29,15.32 22.18,15.32 22.31,15.45 23.58,15.45 23.64,15.51 24.21,15.51
RING2 on IN2 (solid shape): 24.21,15.77 24.21,15.13 23.83,14.75 23.26,14.75 22.75,15.26 22.75,16.02 22.94,16.21 23.77,16.21
RING2 on IN2 (solid shape): 23.58,21.1 23.58,20.78 23.39,20.59 22.44,20.59 22.25,20.4 21.23,20.4 21.23,21.1 21.67,21.54 23.13,21.54
RING2_R on BOTTOM (solid shape): 22.18,16.15 22.18,15.58 22.06,15.45 21.24,15.45 21.24,15.45 20.47,15.45 20.26,15.25 20.19,15.25 20.19,15.17 19.64,14.62 16.21,14.62 15.9,14.94 15.9,15.51 16.09,15.7 17.55,15.7 17.74,15.51 19.32,15.51 19.42,15.61 19.42,15.61 19.54,15.7 19.64,15.82 19.64,15.83 20.15,16.34 21.99,16.34
SA_SNUB on TOP (solid shape): 147.96,65.02 147.96,62.32 147.86,62.22 146.9,62.22 146.79,62.32 146.79,65.04 146.92,65.17 147.81,65.17
SA_SW on BOTTOM (solid shape): 149.63,74.5 149.63,73.36 150.01,72.98 150.01,72.6 149.94,72.54 149.12,72.54 148.8,72.85 148.8,73.49 148.67,73.61 148.17,73.61 148.1,73.68 148.1,74.44 148.29,74.63 149.5,74.63
SA_SW on BOTTOM (solid shape): 150.07,67.9 150.07,65.3 150.58,64.79 151.21,64.79 151.53,64.47 151.53,61.99 151.4,61.87 150.45,61.87 150.45,62.76 149.56,62.76 149.56,61.87 148.17,61.87 148.1,61.93 148.1,64.79 148.29,64.98 148.74,64.98 148.99,65.23 148.99,67.9 149.05,67.96 150.01,67.96
SLEEVE on TOP (solid shape): 23.52,20.27 24.72,20.27 24.79,20.21 24.79,20.08 24.72,20.02 23.45,20.02 23.36,19.93 23.09,19.93 22.98,19.93 22.89,19.9 22.87,19.89 22.56,19.89 22.44,20.02 22.44,20.34 22.56,20.46 23.33,20.46
SLEEVE on BOTTOM (solid shape): 24.34,17.99 24.34,17.73 24.02,17.42 21.29,17.42 21.23,17.48 21.23,18.12 21.61,18.5 23.83,18.5
SLEEVE on BOTTOM (solid shape): 24.72,20.08 24.72,19.58 24.66,19.51 23.71,19.51 23.52,19.7 22.63,19.7 22.44,19.89 22.44,20.34 22.56,20.47 24.34,20.47
SLEEVE_R on BOTTOM (solid shape): 20.19,17.44 20.19,17.37 20.26,17.37 20.28,17.35 20.98,17.35 21.1,17.23 22.05,17.23 22.12,17.16 22.12,16.66 21.99,16.53 20.15,16.53 19.9,16.78 19.18,16.78 19.14,16.79 19.09,16.79 18.59,16.79 18.54,16.79 18.5,16.78 17.55,16.78 17.36,16.59 15.45,16.59 15.32,16.46 14.94,16.46 14.75,16.66 14.75,17.16 15.23,17.64 19.99,17.64
SLEEVE_R on IN1 (solid shape): 15.83,18.37 15.83,16.91 15.2,16.27 14.88,16.27 14.5,16.66 14.5,18.12 14.94,18.56 15.64,18.56
SNUB_+1VALW on BOTTOM (solid shape): 144.23,47.84 144.23,46.25 144.1,46.12 142.13,46.12 142,46.25 142,47.2 142.07,47.27 142.45,47.27 143.15,47.97 144.1,47.97
SW_VCCEOPIO on BOTTOM (solid shape): 99.91,111.91 99.91,110.13 100.92,109.11 101.43,109.11 101.56,108.98 101.56,106.7 101.43,106.57 95.21,106.57 95.02,106.76 95.02,108.22 95.14,108.35 95.59,108.35 95.78,108.54 95.78,109.3 95.91,109.43 97.55,109.43 97.67,109.4 97.79,109.43 98.95,109.43 99.65,110.12 99.65,111.9 99.72,111.97 99.84,111.97
UG_1.2V on BOTTOM (solid shape): 78.38,106.83 78.38,106.13 78.25,106 77.55,106 77.24,106.32 77.24,107.08 77.43,107.27 77.93,107.27
UG_1.2V on BOTTOM (solid shape): 86.51,106.32 86.51,106.19 86.44,106.13 85.62,106.13 85.3,105.81 84.48,105.81 84.35,105.94 84.35,106.19 84.54,106.38 86.44,106.38
UG_1.2V on IN2 (solid shape): 78.68,106.44 78.68,106.38 78.29,105.99 77.56,105.99 77.24,106.32 77.24,107.08 77.43,107.27 77.86,107.27
UG_1.2V on IN2 (solid shape): 85.49,106.19 85.49,105.94 85.36,105.81 83.82,105.81 83.46,106.17 83.46,106.62 83.67,106.83 84.86,106.83
UGATE_CHG on BOTTOM (solid shape): 197.31,34.82 197.39,34.82 198.33,34.82 198.39,34.76 198.39,33.81 197.76,33.81 197.07,34.49 197.06,34.53 197.06,34.57 196.87,34.76 196.11,34.76 196.04,34.82 196.04,34.89 196.11,34.95 197.19,34.95
USB20_VCCA on BOTTOM (solid shape): 174.44,20.75 174.44,18.83 173.95,18.34 173.95,17.08 173.75,16.88 170.43,16.88 170.27,17.04 170.27,19.43 169.82,19.87 169.15,19.87 168.97,20.05 168.97,20.55 169.38,20.96 174.23,20.96
USB30_VCCA on TOP (solid shape): 23.83,44.09 23.83,42.82 23.45,42.44 19.32,42.44 18.75,43.01 17.67,43.01 17.54,42.88 17.54,41.62 17.35,41.43 15.83,41.43 15.32,40.92 14.43,40.92 14.12,41.24 14.12,43.2 15.38,44.47 23.45,44.47
USB30_VCCA on TOP (solid shape): 23.26,65.8 23.26,63.58 23.01,63.33 21.42,63.33 20.53,64.22 20.53,64.47 20.4,64.6 17.86,64.6 17.61,64.34 17.61,63.27 17.61,63.27 17.61,62.94 17.55,62.88 15.7,62.88 15.39,62.57 14.5,62.57 14.18,62.89 14.18,64.86 14.21,64.89 14.21,65.39 15.01,66.19 22.88,66.19
USB30_VCCA on BOTTOM (solid shape): 23.26,65.11 23.26,63.52 22.94,63.2 19.58,63.2 19.32,63.45 19.32,65.11 19.96,65.74 22.63,65.74
USB30_VCCA on BOTTOM (solid shape): 17.55,29.48 17.55,26.63 16.85,25.93 15.07,25.93 14.57,26.43 14.56,26.43 14.31,26.69 9.35,26.69 9.1,26.94 8.21,26.94 8.08,27.07 8.08,28.15 8.72,28.78 14.56,28.78 15.44,29.67 17.36,29.67
USB30_VCCA on BOTTOM (solid shape): 23.9,44.09 23.9,42.94 21.78,40.82 16.91,40.82 16.66,41.08 16.66,42.08 20.05,42.08 20.05,42.03 20.06,41.98 20.07,41.92 20.09,41.88 20.12,41.83 20.16,41.79 20.2,41.76 20.25,41.73 20.3,41.71 20.35,41.7 20.4,41.7 20.46,41.7 20.51,41.71 20.56,41.73 20.6,41.76 20.65,41.79 20.68,41.83 20.71,41.88 20.74,41.92 20.75,41.98 20.76,42.03 20.76,42.08 20.75,42.13 20.74,42.19 20.71,42.23 20.68,42.28 20.65,42.32 20.6,42.35 20.56,42.38 20.51,42.4 20.46,42.41 20.4,42.41 20.35,42.41 20.3,42.4 20.25,42.38 20.2,42.35 20.16,42.32 20.12,42.28 20.09,42.23 20.07,42.19 20.06,42.13 20.05,42.08 16.66,42.08 16.66,44.16 17.04,44.54 23.44,44.54
N17237617 on TOP (solid shape): 202.96,30.25 202.96,28.79 202.96,28.79 202.96,28.67 202.76,28.47 198.33,28.47 197.76,29.04 197.76,30.38 197.82,30.44 202.77,30.44
N17237617 on BOTTOM (solid shape): 205.38,31.39 205.38,29.11 204.93,28.66 204.43,28.66 203.09,27.33 203.09,26.25 202.14,25.3 201.61,25.3 201.61,25.8 200.86,25.8 200.86,25.3 200.42,25.3 200.42,25.8 199.66,25.8 199.66,25.3 199.09,25.3 198.29,26.09 198.29,28.57 197.63,29.23 197.63,30.25 197.82,30.44 202.9,30.44 203.03,30.57 203.03,31.46 203.16,31.58 205.19,31.58
N17415515 on BOTTOM (solid shape): 73.24,125.05 73.24,120.54 72.98,120.29 72.22,120.29 72.22,120.8 71.68,120.8 71.68,120.29 71.43,120.29 71.43,120.8 70.88,120.8 70.88,120.29 70,120.29 69.74,120.54 69.74,124.86 70.19,125.3 72.98,125.3
N18941770 on BOTTOM (solid shape): 153.54,73.92 153.54,72.45 153.11,72.02 151.51,72.02 151.4,72.12 151.4,72.21 151.49,72.29 152.52,72.29 152.83,72.61 152.83,73.49 152.68,73.65 152.17,73.65 152.1,73.72 152.1,74.25 152.21,74.37 153.1,74.37
N18941771 on BOTTOM (solid shape): 151.72,74.38 151.72,73.68 151.59,73.55 150.32,73.55 150.26,73.61 150.26,74.5 150.32,74.57 151.53,74.57
N18941826 on BOTTOM (solid shape): 148.8,68.53 148.8,67.52 148.67,67.39 148.42,67.39 147.78,68.03 147.78,68.41 148.23,68.85 148.48,68.85
N18941826 on BOTTOM (solid shape): 150.01,71.2 150.01,71.07 149.69,70.76 149.69,70.38 149.5,70.19 148.93,70.19 148.93,71.01 149.25,71.33 149.88,71.33
N18941830 on BOTTOM (solid shape): 152.55,73.3 152.55,72.85 152.23,72.54 151.47,72.54 151.4,72.6 151.4,73.23 151.59,73.42 152.42,73.42
N18941830 on BOTTOM (solid shape): 152.61,68.22 152.61,67.9 152.1,67.39 151.15,67.39 151.09,67.46 151.09,67.84 151.59,68.34 152.48,68.34
N18941830 on IN1 (solid shape): 152.23,68.34 152.42,68.34 152.61,68.15 152.61,67.84 152.23,67.46 151.72,67.46 151.15,68.03 151.15,68.22 151.59,68.66 151.91,68.66
N18941830 on IN1 (solid shape): 151.82,73.39 152.45,73.39 152.55,73.3 152.55,72.73 152.04,72.22 152.04,71.58 151.98,71.52 151.28,71.52 151.21,71.58 151.21,73.23 151.4,73.42 151.79,73.42
N18944132 on BOTTOM (solid shape): 156.92,93.29 156.92,91.91 156.51,91.51 156,91.51 155.96,91.55 155.96,92.4 156.15,92.59 156.15,93.35 156.22,93.41 156.79,93.41
N18944143 on BOTTOM (solid shape): 164.35,81.62 164.35,80.35 163.77,79.77 163.19,79.77 163.13,79.84 163.13,80.47 163.52,80.87 163.52,81.49 163.71,81.68 164.28,81.68
N18944156 on BOTTOM (solid shape): 154.07,103.24 154.07,102.15 153.26,101.34 152.76,101.34 152.66,101.44 152.66,102.02 153.25,102.61 153.25,103.26 153.35,103.36 153.96,103.36
N28714507 on BOTTOM (solid shape): 96.6,128.95 96.6,125.63 96.21,125.24 94.53,125.24 94.08,125.69 92.85,125.69 92.67,125.88 92.67,128.96 92.87,129.16 93.43,129.16 93.43,129.17 96.38,129.17
N28714606 on BOTTOM (solid shape): 206.97,29.36 206.97,28.6 206.84,28.47 206.01,28.47 205.89,28.6 205.89,29.36 206.01,29.49 206.84,29.49
N28714606 on BOTTOM (solid shape): 200.55,34.64 200.55,33.74 200.45,33.63 200.08,33.63 199.94,33.77 199.19,33.77 199.12,33.84 199.12,34.66 199.25,34.79 200.4,34.79
N28714606 on IN2 (solid shape): 206.97,29.23 206.97,28.54 206.84,28.41 205,28.41 204.81,28.6 204.81,29.11 205.12,29.42 206.77,29.42
N28714606 on IN2 (solid shape): 200.54,34.57 200.54,33.72 200.41,33.6 199.71,33.6 199.6,33.48 199.6,32.79 199.41,32.6 198.77,32.6 198.64,32.74 198.64,34.31 199.02,34.69 200.42,34.69
N28714612 on BOTTOM (solid shape): 197.63,33.68 197.63,33.68 197.88,33.42 198.39,33.42 198.39,32.54 197.76,32.54 196.49,33.81 196.49,34.06 196.23,34.31 196.11,34.31 196.04,34.38 196.04,34.44 196.11,34.5 196.81,34.5
N28714617 on BOTTOM (solid shape): 102.19,130.35 102.19,126.08 101.19,125.07 101.19,124.47 101.11,124.39 99.57,124.39 99.57,123.75 101.12,123.75 101.19,123.69 101.19,123.09 101.09,122.99 99.51,122.99 98.9,123.6 98.9,124.63 98.9,124.64 98.9,124.89 97.72,126.07 97.45,126.07 97.28,126.24 97.28,130.45 97.52,130.69 101.85,130.69
N28714693 on BOTTOM (solid shape): 217.44,34.06 217.44,26.57 216.71,25.84 214.24,25.84 214.08,26 214.08,27.58 213.38,27.58 213.32,27.52 213.32,26.12 212.81,25.61 212.81,25.11 212.11,24.41 209.44,24.41 209.3,24.55 209.3,24.6 209.29,24.65 209.27,24.71 209.24,24.76 209.21,24.8 209.19,24.82 209.19,28.15 210.75,29.72 210.75,32.23 211,32.23 211,32.18 211.01,32.12 211.03,32.07 211.05,32.02 211.09,31.97 211.12,31.93 211.17,31.9 211.22,31.87 211.27,31.85 211.32,31.84 211.38,31.84 211.43,31.84 211.49,31.85 211.54,31.87 211.59,31.9 211.63,31.93 211.67,31.97 211.71,32.02 211.73,32.07 211.75,32.12 211.76,32.18 211.76,32.23 211.76,32.29 211.74,32.34 211.72,32.39 211.69,32.44 211.65,32.48 211.61,32.52 211.57,32.55 211.52,32.58 211.46,32.59 211.41,32.6 211.35,32.6 211.3,32.59 211.24,32.58 211.19,32.55 211.15,32.52 211.1,32.48 211.07,32.44 211.04,32.39 211.02,32.34 211,32.29 211,32.23 210.75,32.23 210.75,34.13 211.19,34.57 216.93,34.57
N33124472 on TOP (solid shape): 75.56,104.62 75.56,103.79 75.37,103.6 72.88,103.6 72.68,103.8 72.68,104.67 72.88,104.87 75.31,104.87
N39282118 on BOTTOM (solid shape): 156.25,37.96 156.8,37.96 156.8,37.99 156.8,38.5 157.05,38.5 157.05,37.97 157.6,37.97 157.6,38.5 158.07,38.5 158.77,37.81 159.66,37.81 159.72,37.74 159.72,36.92 159.63,36.82 159.31,36.82 159.01,36.52 159.01,34.91 158.86,34.76 156.03,34.76 155.66,35.14 155.66,35.45 155.76,35.71 155.66,35.96 155.66,38.34 155.82,38.5 156.25,38.5
N39880453 on BOTTOM (solid shape): 96.92,105.56 96.92,103.65 96.73,103.46 96.29,103.46 96.22,103.52 96.22,104.29 95.97,104.54 95.14,104.54 95.08,104.6 95.08,105.62 95.14,105.68 96.79,105.68
N40598492 on BOTTOM (solid shape): 177.19,32.21 177.19,31.64 177.06,31.51 175.79,31.51 175.66,31.64 175.66,31.83 176.11,32.28 177.12,32.28
N40598500 on BOTTOM (solid shape): 176.17,36.66 176.17,35.33 176.1,35.27 175.53,35.27 175.41,35.39 175.41,35.96 175.15,36.22 174.64,36.22 174.52,36.35 174.52,36.66 174.64,36.79 176.04,36.79

Small or netless copper shapes (teardrops, artwork), in the pictures only: 16 on TOP, 187 on BOTTOM

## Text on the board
Ref Des/Silkscreen Bottom: SPK | 17"(M2X3L) | 15"(M2.5X5L) | RTC | 17" | (M2X3L) | H11 | 15"/17" | KB | DCIN | TP | BL | LED | IO | Fan | ODD | HDD | BATTERY | DIMM B | SUPPORT DDR4 | SODIMM-ONLY | SODIMM-ONLY SUPPORT DDR4 | DIMM A | EDP
User.Comments: Saijuan | 2017-06-17 | LAD802P | 2016-06-17 | BAL21
Ref Des/Silkscreen Top: OPTANE | Made In Taiwan | 2016-06-17 | Rev:1.0(A00) | BAL21 LA-D802P | PWR | Pb | e1 | LA-D80
User.11: LAYER | NAME | L3 | L1 | L2 | L5 | L4 | L6 | LA-D802P | GND | TOP | VCC | IN1 | IN2 | BOT | LS-XXXXP
User.43: 6.4mil | 3.8 / 3.6
User.44: FIGURE | SIZE | 8.0 | 22.0 | 28.0 | 35.0 | 118.0 | 126.0 | 146.0 | 154.0 | 43.0 | 63.0 | 220.0 | 55.0x24.0 | 63.0x24.0 | 63.0x35.0 | 71.0x31.0 | 79.0x31.0 | 126.0x102.0 | 169.0x146.0 | DRILL CHART: TOP to BOTTOM | ALL UNITS ARE IN MILS | TOLERANCE | +3.0/-3.0 | +2.0/-2.0 | PLATED | NON-PLATED | QTY | 4259 | 19 | 18 | 8 | 6 | 1 | 3 | 7 | 4
